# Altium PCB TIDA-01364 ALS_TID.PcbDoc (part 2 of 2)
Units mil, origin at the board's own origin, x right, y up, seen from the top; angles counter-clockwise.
Board outline 5000 x 4000 mil, 4 copper layers (Layer 1 - Top Layer, Layer 2 - GND, Layer 3 - PWR, Layer 4 - Bottom Layer), stack 61.434 mil thick; 133 components, 87 nets, 390 pads, 185 vias.
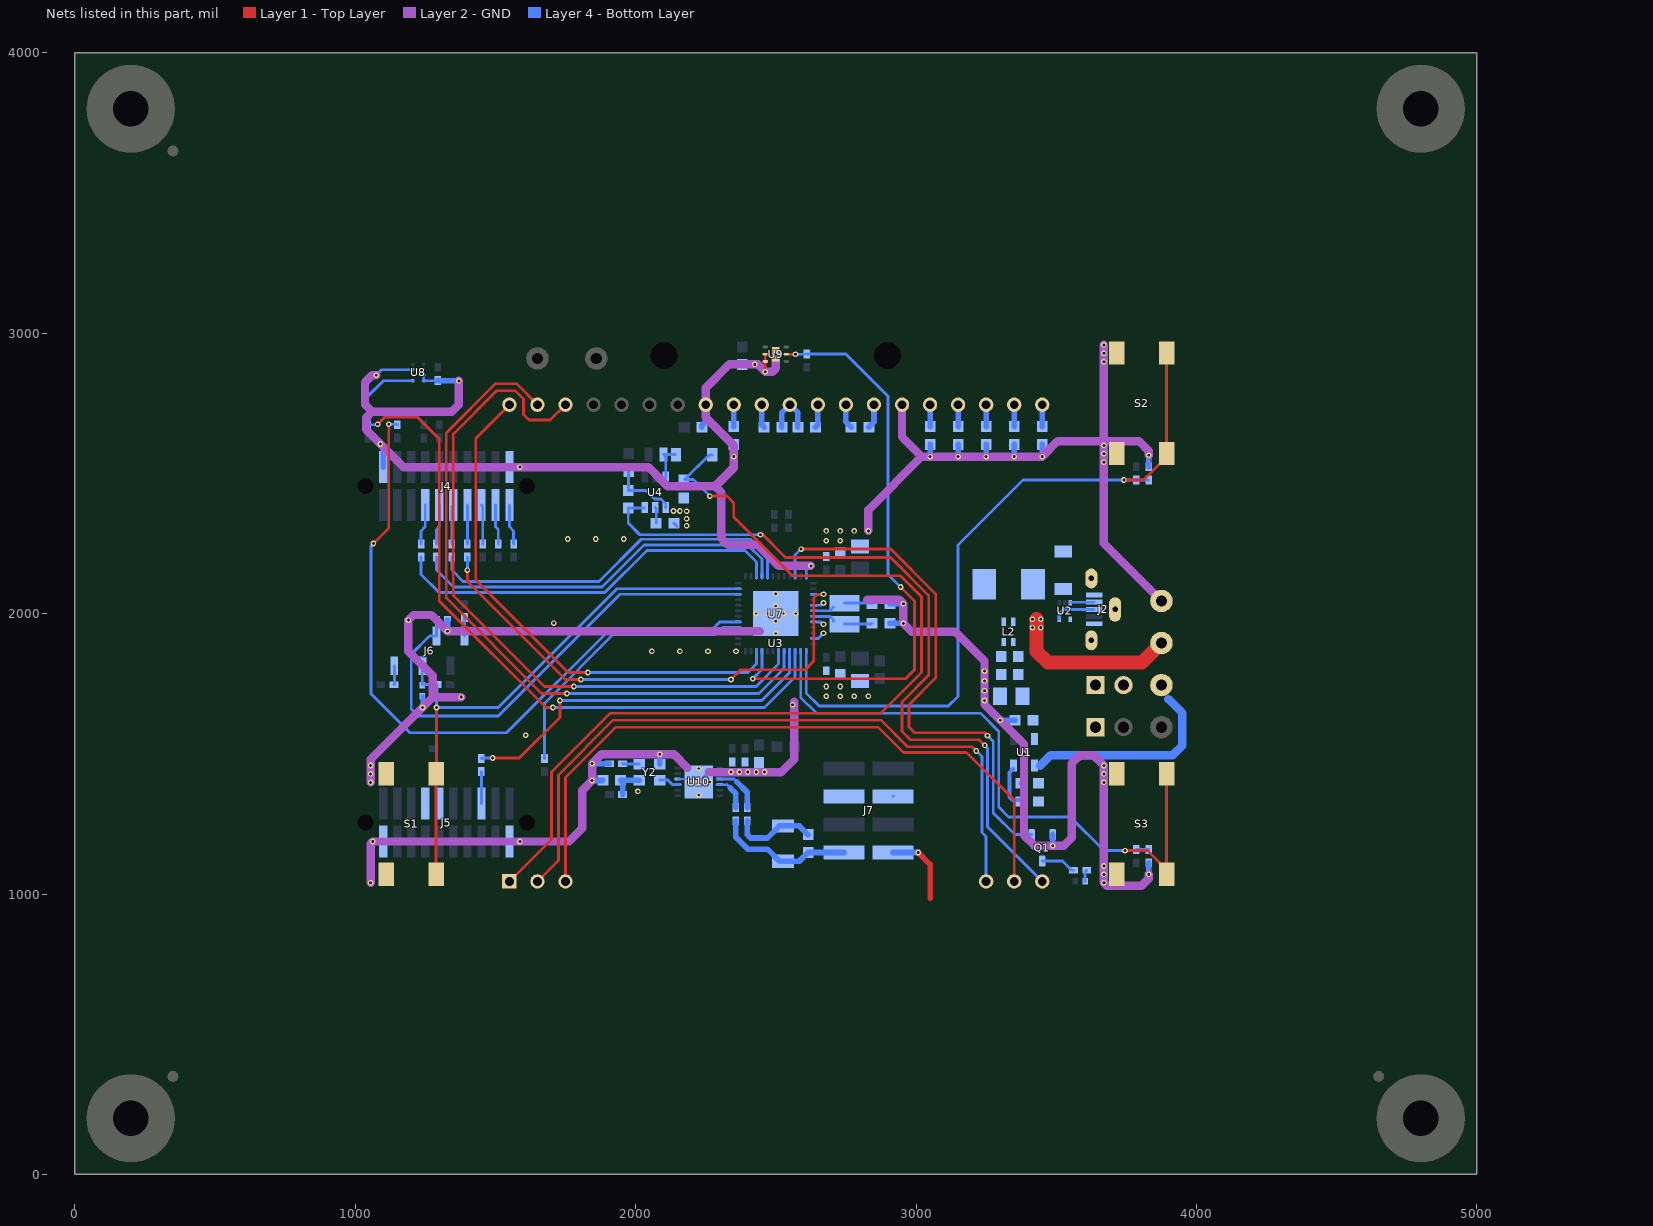
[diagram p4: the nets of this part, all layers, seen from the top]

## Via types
v1: diameter 20, hole 10, Layer 1 - Top Layer to Layer 4 - Bottom Layer, tented both sides, 171 vias
v2: diameter 19.68, hole 7.87, Layer 1 - Top Layer to Layer 4 - Bottom Layer, tented both sides, 14 vias

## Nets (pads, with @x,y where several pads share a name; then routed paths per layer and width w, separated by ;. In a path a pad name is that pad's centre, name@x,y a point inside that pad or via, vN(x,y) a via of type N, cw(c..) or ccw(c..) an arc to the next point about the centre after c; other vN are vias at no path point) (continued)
GND: C2.2 C3.2 C4.2 C6.2 C7.2 C9.2 C10.2 C12.2 C13.2 C14.2 C15.2 C16.2 C17.1 C18.1 C19.2 C20.1 C21.1 C22.2 C23.1 C24.1 C25.1 C26.2 C27.2 C28.1 C29.2 C30.2 C31.1 C32.2 C33.2 C35.2 J4.2 J4.20 J5.1 J5.19 J6.5 L3.2 Q1.2 R27.2 R28.1 S1.3 S1.4 S2.3 S2.4 S3.3 S3.4 TP4.1 U1.2 U3.26 U3.33 U4.4 U5.2 U6.2 U7.36 U7.41 U7.44 U7.47 U7.49 U8.B2 U8.C1 U8.D1 U9.2 U9.3 U9.7 U10.4 U10.8 U10.13 Y2.2 | length 14551.3
  Layer 1 - Top Layer w10: v1(2462.6,2862.4) U9.3@2462.6,2899.21 U9.2@2462.6,2925
  Layer 2 - GND w30: v1(1055,1040) 1055,1180 v1(1062.48,1187.48) v1(1587.52,1187.48) 1762.48,1187.48 1810,1235 1810,1370 v1(1845,1405) v1(1845,1465) 1878.58,1498.58 v1(2086.42,1498.58) 2136.42,1498.58 2185,1450 ; v1(1055,1398.27) v1(1055,1428.27) v1(1055,1458.27) 1055,1480 v1(1240,1665) 1277.3,1702.3 ; v1(1075,2850) 1060,2850 1035,2825 1035,2745 1060,2720 ; v1(1370,2830) 1370,2745 1345,2720 1060,2720 ; v1(1378.38,1702.3) 1277.3,1702.3 ; 2260,1435 v1(2340,1435) v1(2370,1435) v1(2400,1435) v1(2430,1435) v1(2460,1435) 2520,1435 2565,1480 2565,1685 ; 2442.13,1937.13 v1(1329.37,1937.13) 1271.5,1995 1207.87,1995 v1(1189.69,1976.81) 1189.69,1865.31 1277.3,1777.7 1277.3,1702.3 ; v2(2500,2925) 2500,2875 2487.4,2862.4 v1(2462.6,2862.4) 2436.5,2888.5 v1(2425,2888.5) 2333.5,2888.5 2250,2805 U3.33@2250,2745 2250,2700 2350,2600 v1(2350,2560) 2350,2520 2284,2454 ; v1(2625,2170) 2510,2170 2435,2245 2330,2245 2305,2270 2305,2433 2284,2454 ; 2825,2050 2940,2050 v1(2955,2035) v1(2955,1965) 2985,1935 3140,1935 3244,1831 v1(3244,1795) v1(3244,1760) v1(3244,1725) v1(3244,1690) 3244,1676.01 v1(3300,1620) 3385,1535.01 v1(3385,1500) 3385,1209.32 3421.91,1172.4 v1(3487.4,1172.4) 3527.4,1172.4 3555,1200 3555,1465 3585,1495 3633.27,1495 v1(3670,1458.27) v1(3670,1428.27) v1(3670,1398.27) v1(3670,1100) v1(3670,1070) v1(3670,1040) 3680.01,1030 3805,1030 3830,1055 v1(3830,1070) ; v1(2830,2295) 2830,2370 3020,2560 ; U3.26@2950,2745 2950,2630 3020,2560 ; v1(3670,2958.27) v1(3670,2928.27) v1(3670,2898.27) 3670,2615 ; v1(3830,2565) 3830,2580 3795,2615 3670,2615 ; TP4.1@3875,2045 3670,2250 v1(3670,2540) v1(3670,2570) v1(3670,2600) 3670,2615 ; 1060,2720 1040,2700 1040,2655 v1(1090,2605) 1172.48,2522.52 v1(1587.52,2522.52) 2045.48,2522.52 2114,2454 2284,2454 ; 3020,2560 v1(3050,2560) v1(3150,2560) v1(3250,2560) v1(3350,2560) v1(3450,2560) 3505,2615 3670,2615
  Layer 4 - Bottom Layer w8: U10.4@2150.2,1409.84 2215.16,1409.84 v2(2225,1400) 2254.53,1429.53 U10.8@2299.8,1429.53
  Layer 4 - Bottom Layer w10: v1(1075,2850) 1094.85,2869.85 U8.B2@1205.31,2869.85 ; U8.C1@1244.68,2850.16 U8.D1@1244.68,2830.48 C28.1@1289.09,2830.48 ; C28.1@1289.09,2825.48 C28.1@1295,2831.38 ; R28.1@1974,2439.5 R28.1@1974.99,2439.5 ; C7.2@1975,2507.5 R28.1@1975,2439.5 ; U4.4@2107,2379.33 U4.4@2107.46,2378.87 U4.4@2107.46,2385.36 ; U4.4@2107,2392.3 2090.3,2409 2067,2409 2036.5,2439.5 R28.1@1974.99,2439.5 ; C35.2@2136.5,2322 C35.2@2147.5,2311 ; U7.36@2608.27,2127 U7.36@2608.27,2133.86 2608.27,2153.27 v1(2625,2170) ; U7.47@2627,1911.42 U7.47@2633.86,1911.42 2651.42,1911.42 v1(2670,1930) ; U7.44@2627,1970.47 U7.44@2633.86,1970.47 2661.53,1970.47 v1(2670,1962) ; U7.41@2627,2029.53 U7.41@2633.86,2029.53 2661.53,2029.53 v1(2670,2038)
  Layer 4 - Bottom Layer w15: v1(1240,1665) U6.2@1240,1705.32 ; C3.2@3373.5,1395 3385,1406.5 U1.2@3385,1457.76 v1(3385,1500)
  Layer 4 - Bottom Layer w20: v1(1062.48,1187.48) J5.19@1100,1187.48 ; v1(1090,2605) 1100,2595 J4.20@1100,2522.52 ; J6.5@1189.69,1919.96 v1(1189.69,1976.81) ; C28.1@1295,2831.38 1296.38,2830 v1(1370,2830) ; v1(1329.37,1937.13) U5.2@1329.37,1976.81 ; C23.1@1338.62,1702.3 v1(1378.38,1702.3) ; J5.1@1550,1187.48 v1(1587.52,1187.48) ; J4.2@1550,2522.52 v1(1587.52,2522.52) ; v1(1845,1405) C32.2@1883.5,1405 ; v1(1845,1465) R27.2@1906.38,1465 ; Y2.2@2086.42,1463.54 v1(2086.42,1498.58) ; C6.2@2236.5,2665 2236.5,2671.5 2250,2685 U3.33@2250,2745 ; v1(2350,2560) C9.2@2350,2603.5 ; C27.2@2906.5,1965 v1(2955,1965) ; C26.2@2906.5,2035 v1(2955,2035) ; v1(3050,2560) C10.2@3050,2603.5 ; v1(3150,2560) C12.2@3150,2603.5 ; v1(3250,2560) C13.2@3250,2603.5 ; v1(3300,1620) C4.2@3353.5,1620 ; v1(3350,2560) C14.2@3350,2603.5 ; v1(3450,2560) C15.2@3450,2603.5 ; v1(3487.4,1172.4) Q1.2@3487.4,1212.24 ; v1(3830,1070) C25.1@3830,1111.38 ; C24.1@3830,2523.62 v1(3830,2565)
  Layer 4 - Bottom Layer w25: C29.2@2380,2888.5 v1(2425,2888.5)
  other v1: 2008,1366 1608,1566 2560,1675 2680,1705 2730,1705 2780,1705 2830,1705 2680,1740 2730,1740 2058,1866 2158,1866 2258,1866 2358,1866 1708,1966 2680,2260 2730,2260 1758,2266 1858,2266 1958,2266 2680,2295 2730,2295 2780,2295 2182,2313 2182,2338 2182,2365 2135,2366 2158,2366
  other v2: 2225,1352.76 2185.63,1400 2264.37,1400 2225,1447.24 2500,1929.13 2500,1972.44 2429.13,2000 2472.44,2000 2527.56,2000 2570.87,2000 2500,2027.56 2500,2070.87
HDC_DRDY: R23.1 U7.3 U8.D2 | length 2730.7
  Layer 1 - Top Layer w10: v1(1080,2675) 1105,2700 1222.5,2700 1300,2622.5 1300,2045 1680,1665 v1(1705,1665)
  Layer 4 - Bottom Layer w10: v1(1080,2675) 1078.62,2673.62 R23.1@1045,2673.62 1045,2775 1100.48,2830.48 U8.D2@1205.31,2830.48 ; v1(1705,1665) 2460,1665 2568.9,1773.9 U7.3@2568.9,1866.14 U7.3@2568.9,1873
HFXIN: C26.1 U7.42 Y1.1 | length 183.9
  Layer 4 - Bottom Layer w10: U7.42@2627,2009.84 2692.84,2009.84 Y1.1@2706,2023 ; Y1.1@2745,2037.4 2841.1,2037.4 C26.1@2843.5,2035
HFXOUT: C27.1 U7.43 Y1.2 | length 187.9
  Layer 4 - Bottom Layer w10: U7.43@2627,1990.16 2692.84,1990.16 2706,1977 Y1.2@2706,1973 ; Y1.2@2745,1962.6 2841.1,1962.6 C27.1@2843.5,1965
IN0A: R24.2 U10.9 | length 181.8
  Layer 4 - Bottom Layer w10: U10.9@2290,1409.84 U10.9@2299.8,1409.84 2351.16,1409.84 2361,1400
  Layer 4 - Bottom Layer w20: 2361,1400 2398,1363 R24.2@2398,1308.62
IN0A_1: C34.1 L7.2 R24.1 | length 302.2
  Layer 4 - Bottom Layer w20: R24.1@2398,1261.38 2398,1212 2410,1200 2470,1200 2512.99,1242.99 L7.2@2525,1242.99 2583.5,1242.99 C34.1@2615,1211.5
IN0B: R26.2 U10.10 | length 130.3
  Layer 4 - Bottom Layer w10: U10.10@2290,1390 2325.84,1390.16 2337,1379
  Layer 4 - Bottom Layer w20: 2337,1379 2357,1359 R26.2@2357,1308.62
IN0B_1: C34.2 J7.8 L7.1 R26.1 | length 481.3
  Layer 4 - Bottom Layer w20: R26.1@2357,1261.38 2357,1203 2400,1160 2470,1160 L7.1@2512.99,1117.01 ; L7.1@2525,1117.01 2583.5,1117.01 C34.2@2615,1148.5 2615.5,1148 J7.8@2743.1,1148
IN1B_1: J7.4
LCD_A0: U3.38 U7.6 | length 2518.4
  Layer 1 - Top Layer w10: U3.38@1750,2745 1695,2690 1620,2690 1600,2710 1600,2765 1570,2795 1505,2795 1350,2640 1350,2065 1675,1740 v1(1780,1740)
  Layer 4 - Bottom Layer w10: v1(1780,1740) 2430,1740 2509.84,1819.84 U7.6@2509.84,1866.14 U7.6@2509.84,1873
LED_1: Q1.1 U7.34 | length 1917.9
  Layer 1 - Top Layer w10: v1(2590,2230) 2910,2230 3070,2070 3070,1770 2975,1675 2975,1595 2995,1575 3245,1575 v1(3255,1565)
  Layer 4 - Bottom Layer w10: U7.34@2568.9,2127 U7.34@2568.9,2133.86 2568.9,2208.9 v1(2590,2230) ; v1(3255,1565) 3275,1545 3275,1290 3352.76,1212.24 Q1.1@3412.6,1212.24
LED_CA1: U3.2 U3.18 | length 2506.9
  Layer 1 - Top Layer w10: U3.2@1650,1045 1725,1120 1725,1425 1920,1620 2875,1620 2970,1525 3200,1525 v1(3215,1510)
  Layer 4 - Bottom Layer w10: v1(3215,1510) 3235,1490 3235,1220 3250,1205 U3.18@3250,1045
LED_CA2: U3.3 U3.19 | length 2442.3
  Layer 1 - Top Layer w10: U3.3@1750,1045 1750,1415 1930,1595 2865,1595 2955,1505 3180,1505 3350,1335 U3.19@3350,1045
NCSB_LCD: U3.40 U7.10 | length 1877.3
  Layer 1 - Top Layer w10: U3.40@1550,2745 1430,2625 1430,2120 1760,1790 v1(1830,1790)
  Layer 4 - Bottom Layer w10: v1(1830,1790) 2400,1790 2431.1,1821.1 U7.10@2431.1,1866.14 U7.10@2431.1,1873
NCSB_RF: R12.2 U7.39 | length 1802
  Layer 1 - Top Layer w10: v1(1400,2155) 1400,2115 1750,1765 v1(1805,1765) ; v1(2340,1765) 2375,1800 2605,1800 2635,1830 2635,2055 2648.9,2068.9 v1(2670,2068.9)
  Layer 4 - Bottom Layer w10: v1(1400,2155) R12.2@1400,2201.38 ; v1(1805,1765) v1(2340,1765) ; U7.39@2627,2068.9 U7.39@2633.86,2068.9 v1(2670,2068.9)
NetC2_1: C2.1 J1.1 L1.2
NetC4_1: C4.1 J3.1 U1.5
NetC5_1: C5.1 U3.31 | length 83.5
  Layer 4 - Bottom Layer w20: U3.31@2450,2745 2450,2673.5 C5.1@2458.5,2665
NetC5_2: C5.2 C8.1 U3.30 | length 183.6
  Layer 4 - Bottom Layer w20: C5.2@2521.5,2665 2521.5,2716.5 U3.30@2550,2745 2578.5,2716.5 C8.1@2578.5,2665
NetC8_2: C8.2 U3.29 | length 83.5
  Layer 4 - Bottom Layer w20: C8.2@2641.5,2665 2650,2673.5 U3.29@2650,2745
NetC9_1: C9.1 U3.32 | length 78.5
  Layer 4 - Bottom Layer w20: C9.1@2350,2666.5 U3.32@2350,2745
NetC10_1: C10.1 U3.25 | length 78.5
  Layer 4 - Bottom Layer w20: C10.1@3050,2666.5 U3.25@3050,2745
NetC11_1: C11.1 U3.28 | length 87.7
  Layer 4 - Bottom Layer w20: U3.28@2750,2745 2750,2683.5 C11.1@2768.5,2665
NetC11_2: C11.2 U3.27 | length 87.7
  Layer 4 - Bottom Layer w20: C11.2@2831.5,2665 2850,2683.5 U3.27@2850,2745
NetC12_1: C12.1 U3.24 | length 78.5
  Layer 4 - Bottom Layer w20: C12.1@3150,2666.5 U3.24@3150,2745
NetC13_1: C13.1 U3.23 | length 78.5
  Layer 4 - Bottom Layer w20: C13.1@3250,2666.5 U3.23@3250,2745
NetC14_1: C14.1 U3.22 | length 78.5
  Layer 4 - Bottom Layer w20: C14.1@3350,2666.5 U3.22@3350,2745
NetC15_1: C15.1 U3.21 | length 78.5
  Layer 4 - Bottom Layer w20: C15.1@3450,2666.5 U3.21@3450,2745
NetC16_1: C16.1 D2.1 U3.1 | length 3372.3
  Layer 1 - Top Layer w10: U3.1@1550,1045 1700,1195 1700,1435 1910,1645 2875,1645 3020,1790 3020,2060 2945,2135 2560,2135 2350,2345 2350,2394.7 2325.7,2419 v1(2265,2419)
  Layer 4 - Bottom Layer w10: v1(2265,2419) 2206,2478 2174.5,2478 2262.5,2566 D2.1@2273.47,2566
NetC32_1: C32.1 R25.1 Y2.4 | length 120.6
  Layer 4 - Bottom Layer w10: C32.1@1946.5,1405 C32.1@1947.95,1406.46
  Layer 4 - Bottom Layer w20: C32.1@1946.5,1405 1953.62,1397.87 R25.1@1953.62,1355 ; C32.1@1947.95,1406.46 Y2.4@2013.58,1406.46
NetC35_1: C35.1 U4.5 | length 58.3
  Layer 4 - Bottom Layer w10: U4.5@2070.06,2378.87 2073.5,2375.42 C35.1@2073.5,2322
NetD2_2: D2.2 L4.2 U4.3 | length 125.3
  Layer 4 - Bottom Layer w10: U4.3@2107.46,2487.13 2107.46,2559.24 L4.2@2099.45,2567.25 D2.2@2141.28,2567.25
NetD3_1: D3.1 J5.12 J5.14
NetD4_1: D4.1 R21.2 | length 42.4
  Layer 4 - Bottom Layer w10: D4.1@3602.72,1045 3602.72,1079.09 R21.2@3608.62,1085
NetJ4_1: J4.1 R15.2 | length 145.1
  Layer 4 - Bottom Layer w10: J4.1@1550,2387.48 1550,2310 1565,2295 R15.2@1565,2248.62
NetJ4_3: J4.3 R14.1 | length 143
  Layer 4 - Bottom Layer w10: J4.3@1500,2387.48 1500,2310 1510,2300 R14.1@1510,2248.62
NetJ4_5: J4.5 R13.1 | length 140.9
  Layer 4 - Bottom Layer w10: J4.5@1450,2387.48 1455,2382.48 R13.1@1455,2248.62
NetJ4_7: J4.7 R12.1 | length 138.9
  Layer 4 - Bottom Layer w10: R12.1@1400,2248.62 J4.7@1400,2387.48
NetJ4_9: J4.9 R8.2 | length 140.9
  Layer 4 - Bottom Layer w10: R8.2@1345,2248.62 1345,2382.48 J4.9@1350,2387.48
NetJ4_11: J4.11 R7.2 | length 143
  Layer 4 - Bottom Layer w10: R7.2@1290,2248.62 1290,2300 1300,2310 J4.11@1300,2387.48
NetJ4_13: J4.13 R5.1 | length 145.1
  Layer 4 - Bottom Layer w10: R5.1@1235,2248.62 1235,2295 1250,2310 J4.13@1250,2387.48
NetJ5_6: J5.6 R11.1 | length 113.9
  Layer 4 - Bottom Layer w10: J5.6@1450,1322.52 R11.1@1450,1436.38
NetJ6_1: J6.1 R3.2 | length 73.2
  Layer 4 - Bottom Layer w10: J6.1@1389.69,1919.96 R3.2@1389.69,1993.19
NetJ6_6: J6.6 R9.2 | length 67.4
  Layer 4 - Bottom Layer w10: R9.2@1138.31,1746.81 1139.69,1748.19 J6.6@1139.69,1813.66
NetL1_1: L1.1 L2.3
NetL2_2: L2.2 L3.1
NetQ1_3: Q1.3 R21.1 | length 124.9
  Layer 4 - Bottom Layer w10: Q1.3@3450,1117.76 3522.24,1117.76 3555,1085 R21.1@3561.38,1085
NetR1_2: R1.2 U1.3 | length 148.4
  Layer 4 - Bottom Layer w15: U1.3@3345,1445 3333,1433 3333,1347 3345,1335 R1.2@3373.5,1335
NetR27_1: R27.1 Y2.1 | length 60.6
  Layer 4 - Bottom Layer w10: R27.1@1953.62,1465 1955.08,1463.54 Y2.1@2013.58,1463.54
NetR28_2: R28.2 U3.20 U4.6 | length 2699.9
  Layer 1 - Top Layer w10: v1(2445.5,2281) 2450,2281 2452,2283 2535,2200 2910,2200 3045,2065 3045,1780 2950,1685 2950,1580 2980,1550 3225,1550 v1(3245,1530)
  Layer 4 - Bottom Layer w10: U4.6@2030.3,2376.5 R28.2@1974,2376.5 1974,2322 2013,2283 2015,2281 v1(2445.5,2281) ; v1(3245,1530) 3255,1520 3255,1240 U3.20@3450,1045
NetU10_3: U10.3 Y2.3 | length 80.3
  Layer 4 - Bottom Layer w10: Y2.3@2086.42,1406.46 2114.54,1406.46 2130.84,1390.16 U10.3@2150.2,1390.16 U10.3@2160,1390.16
NRST_EM: R11.2 U7.4 | length 1344.7
  Layer 1 - Top Layer w10: v1(1490,1485) 1585,1485 1730,1630 v1(1730,1690)
  Layer 4 - Bottom Layer w10: R11.2@1450,1483.62 1451.38,1485 v1(1490,1485) ; v1(1730,1690) 2450,1690 2549.21,1789.21 U7.4@2549.21,1866.14 U7.4@2549.21,1873
NRST_LCD: U3.39 U7.5 | length 2469.5
  Layer 1 - Top Layer w10: U3.39@1650,2745 1575,2820 1500,2820 1325,2645 1325,2055 1665,1715 v1(1755,1715)
  Layer 4 - Bottom Layer w10: v1(1755,1715) 2440,1715 2529.53,1804.53 U7.5@2529.53,1866.14 U7.5@2529.53,1873
OPT_INT: R22.1 U7.9 U9.5 | length 2149.8
  Layer 1 - Top Layer w10: v1(2417.5,1767.5) 2962.5,1767.5 2995,1800 2995,2045 v1(2945,2095) ; U9.5@2537.4,2925 v1(2570,2925)
  Layer 4 - Bottom Layer w10: v1(2417.5,1767.5) 2450.79,1800.79 U7.9@2450.79,1866.14 U7.9@2450.79,1873 ; v1(2570,2925) 2609.39,2925 R22.1@2610,2925.61 2749.39,2925.61 2900,2775 2900,2140 v1(2945,2095)
P3.4: R5.2 U7.27 | length 1420.5
  Layer 4 - Bottom Layer w10: R5.2@1235,2201.38 1235,2140 1300,2075 1890,2075 2040,2225 2390,2225 2431.1,2183.9 U7.27@2431.1,2127
P3.5: R7.1 U7.28 | length 1382.4
  Layer 4 - Bottom Layer w10: R7.1@1290,2201.38 1290,2155 1350,2095 1880,2095 2030,2245 2400,2245 2450.79,2194.21 U7.28@2450.79,2127
P3.6: R8.1 U7.29 | length 1353.1
  Layer 4 - Bottom Layer w10: R8.1@1345,2201.38 1345,2155 1385,2115 1870,2115 2020,2265 2410,2265 2470.47,2204.53 U7.29@2470.47,2127
SBWTCK: J6.3 U5.1 U7.22 | length 1736.7
  Layer 4 - Bottom Layer w10: U5.1@1290,1981.81 1289.69,1981.5 J6.3@1289.69,1919.96 1264.96,1919.96 1200,1855 1200,1660 1225,1635 1510,1635 1943.9,2068.9 U7.22@2373,2068.9
SBWTDIO: C23.2 J6.4 R18.1 S1.1 S1.2 U6.1 U7.23 | length 2055.2
  Layer 1 - Top Layer w10: S1.2@1288.58,1070.87 S1.1@1288.58,1429.13 1290,1430.55 v1(1290,1665)
  Layer 4 - Bottom Layer w10: J6.4@1239.69,1813.66 1239.37,1813.35 1239.37,1746.81 1239.86,1747.3 R18.1@1291.38,1747.3 C23.2@1291.38,1702.3 1290,1700.92 v1(1290,1665) 1510,1665 1933.58,2088.58 U7.23@2366.14,2088.58 U7.23@2373,2088.58
SENSOR1: J7.7 | length 270.5
  Layer 1 - Top Layer w20: v1(3008,1148) 3050,1106.01 3050,985
  Layer 4 - Bottom Layer w20: J7.7@2917.9,1148 v1(3008,1148)
SENSOR2: J7.3 | length 2.8
  Layer 4 - Bottom Layer w10: J7.3@2917.9,1348 J7.3@2919.9,1350
UART_CTS: R2.2 U7.17 | length 2556.5
  Layer 1 - Top Layer w10: v1(1065,2250) 1120,2305 v1(1120,2675)
  Layer 4 - Bottom Layer w10: v1(1065,2250) 1056,2241 1056,1714 1195,1575 1540,1575 1910,1945 2274.53,1945 2300,1970.47 U7.17@2366.14,1970.47 U7.17@2373,1970.47 ; v1(1120,2675) 1148.62,2675 R2.2@1150,2673.62
UART_RTS: R10.1 U7.16 | length 1006.5
  Layer 4 - Bottom Layer w10: R10.1@1675,1483.62 1675,1680 1920,1925 2285,1925 2310.79,1950.79 U7.16@2366.14,1950.79 U7.16@2373,1950.79
USB_D_N: J2.2 U2.3 | length 85.8
  Layer 4 - Bottom Layer w10: U2.3@3549.69,2039.53 3550.75,2040.59 J2.2@3635,2040.59
USB_D_P: J2.3 U2.5 | length 150.6
  Layer 4 - Bottom Layer w10: U2.5@3510.31,1980.47 3510.31,2000.31 3525,2015 J2.3@3635,2015
USB_GND: C1.2 D1.1 J2.5 J2.6 J2.7 J2.8 L2.1 U2.4
USR_BTN_1: C24.2 R19.1 S2.1 S2.2 U7.1 | length 2604.5
  Layer 1 - Top Layer w10: v1(3741.38,2476.38) 3811.38,2476.38 3893.58,2558.58 S2.2@3893.58,2570.86 S2.1@3893.58,2929.13
  Layer 4 - Bottom Layer w10: U7.1@2608.27,1873 U7.1@2608.27,1866.14 2608.27,1716.73 2655,1670 3115,1670 3150,1705 3150,2245 3381.38,2476.38 v1(3741.38,2476.38) R19.1@3785,2476.38 C24.2@3830,2476.38
USR_BTN_2: C25.2 R20.1 S3.1 S3.2 U7.2 | length 2334.3
  Layer 1 - Top Layer w10: v1(3745,1155) 3825,1155 S3.2@3893.58,1086.42 ; S3.2@3893.58,1070.87 S3.2@3893.58,1086.42 ; S3.1@3893.58,1429.13 S3.2@3893.58,1086.42
  Layer 4 - Bottom Layer w10: U7.2@2588.58,1873 U7.2@2588.58,1866.14 2588.58,1701.42 2645,1645 3230,1645 3295,1580 3295,1310 3330,1275 3550,1275 3670,1155 v1(3745,1155) 3781.38,1155 R20.1@3785,1158.62 C25.2@3830,1158.62
V_INPUT: C3.1 J1.2 R1.1 TP2.1 U1.1 | length 723.3
  Layer 4 - Bottom Layer w30: 3442.49,1457.49 3480,1495 3915,1495 3950,1530 3950,1645 3900,1695
VBUS: C1.1 D1.2 J2.1 L2.4 TP1.1 | length 605.6
  Layer 1 - Top Layer w50: 3430,1980 3430,1865 3470,1825 3805,1825 TP1.1@3875,1895
  other v1: 3415,1950 3445,1950 3415,1980 3445,1980
pads on no net: FID1.1 FID2.1 FID3.1 FID4.1 FID5.1 FID6.1 H1.1 H2.1 H3.1 H4.1 H5.0 H6.0 H7.0 H8.0 J2.4 J4.4 J4.6 J4.8 J4.10 J4.15 J4.16 J4.17 J4.19 J4.MH1 J4.MH2 J5.2 J5.4 J5.5 J5.7 J5.8 J5.9 J5.10 J5.11 J5.13 J5.15 J5.16 J5.17 J5.18 J5.20 J5.MH1 J5.MH2 J7.1 J7.2 J7.5 J7.6 SH-J1.0 SH-J2.0 SH-J3.0 SH-J4.0 U1.4 U2.1 U2.2 U7.7 U7.8 U7.12 U7.13 U7.14 U7.15 U7.30 U7.33 U7.35 U7.38 U7.40 U7.45 U7.46 U8.C2 U10.11 U10.12

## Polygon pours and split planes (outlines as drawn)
GND on Layer 4 - Bottom Layer "GND_L04_P012" (solid, remove dead copper, pour order 12): 2188.73,2294.73 2104,2294.73 2104,2348 2098,2354 2092,2360 2092,2403 2137.73,2403 2144.73,2410 2168.73,2434 2194,2434 2194,2382.98 2193.02,2382 2193.02,2299.02
NetC4_1 on Layer 4 - Bottom Layer "Layer 1 - CIN1 - Top Layer-No Net" (solid, remove dead copper, pour order 10): 3655,1645 3390,1645 3390,1545 3410,1525 3655,1525 3675,1545 3675,1625
GND on Layer 2 - GND "GND_L02_P014" (solid, remove dead copper, pour order 14): 2193,2331 2193,2398 2120.1,2398 2107.46,2385.36 2108,2384.82 2108,2331 2168,2331
GND on Layer 2 - GND "Layer 2 - GND- GND" (solid, remove dead copper, pour order 8): 2275,1340 1610,1340 1550,1400 1550,2105 1780,2335 2375,2335 2410,2300 2580,2130 2580,1665 2580,1475 2525,1420 2275,1420
GND on Layer 2 - GND "Layer 2 - SHLD1 - GND-GND" (solid, remove dead copper, pour order 9): 3005,1655 2375,1655 2375,2310 3005,2310
GND on Layer 3 - PWR "Layer 2 - GND- GND" (solid, remove dead copper, pour order 7): 2275,1340 1610,1340 1550,1400 1550,2105 1780,2335 2375,2335 2410,2300 2580,2130 2580,1665 2580,1475 2525,1420 2275,1420
GND on Layer 1 - Top Layer "Layer 2 - GND- GND" (solid, remove dead copper, pour order 6): 2275,1340 1610,1340 1550,1400 1550,2105 1780,2335 2375,2335 2410,2300 2580,2130 2580,1665 2580,1475 2525,1420 2275,1420

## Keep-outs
Keep-Out Layer:
  text ".Layer_Name" at 577,-858.49 h60

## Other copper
Layer 1 - Top Layer:
  region net SENSOR1: 400,0 400,400 1000,400 1000,1000 4000,1000 4000,3000 1000,3000 1000,400 0,400 0,3600 400,3600 400,4000 4600,4000 4600,3600 5000,3600 5000,400 4600,400 4600,0
  region net GND: 3745,2525 3655,2525 3655,2615 3745,2615
  region net GND: 3745,2883.27 3655,2883.27 3655,2973.27 3745,2973.27
  region net GND: 3745,1025 3655,1025 3655,1115 3745,1115
  region net GND: 1140,1383.27 1040,1383.27 1040,1473.27 1140,1473.27
  region net GND: 1140,1025 1040,1025 1040,1115 1140,1115
  region net GND: 3745,1383.27 3655,1383.27 3655,1473.27 3745,1473.27
  text ".Layer_Name" at 577,-858.49 h60
Layer 2 - GND:
  region net GND: 2175,1340 2275,1340 2275,1460 2175,1460
Layer 3 - PWR:
  region net 3P3V: 3700,1545 3700,1625 3720,1645 3900,1645 3920,1625 3920,1545 3900,1525 3720,1525
Layer 4 - Bottom Layer:
  region net USB_GND: 3535,1990 3571,1990 3593,1968 3678,1968 3685,1975 3685,2075 3675,2085 3615,2085 3600,2100 3600,2155 3570,2185 3355,2185 3322,2152 3322,1947 3310,1935 3212,1935 3200,1947 3200,2225 3280,2305 3660,2305 3755,2210 3755,1890 3725,1860 3550,1860 3535,1875
  region net NetL1_1: 3338,1825 3385,1825 3385,1895 3360,1920 3338,1920
  region net NetL2_2: 3325,1825 3285,1825 3285,1895 3310,1920 3325,1920
  region net GND: 3324,1805 3324,1675 3229,1675 3229,1805
  region net NetD3_1: 1235,1265 1315,1265 1315,1425 1290,1450 1260,1450 1235,1425
  region net AVCC: 2622,1897 2622,1868 2665,1825 2750,1825 2775,1800 2890,1800 2890,1910 2673,1910 2660,1897
  region net GND: 2665,1815 2740,1815 2770,1785 2840,1785 2840,1690 2675,1690 2665,1700
  region net 3P3V: 2622,2103 2622,2132 2665,2175 2750,2175 2775,2200 2840,2200 2840,2090 2673,2090 2660,2103
  region net GND: 2665,2185 2740,2185 2770,2215 2840,2215 2840,2310 2675,2310 2665,2300
  region net 3P3V: 3700,1545 3700,1625 3720,1645 3900,1645 3920,1625 3920,1545 3900,1525 3720,1525
  region net 3P3V: 2195,2645 2195,2750 2170,2775 2025,2775 2005,2755 2005,2665 2025,2645
  region net 3P3V: 1954.5,2626 2009.5,2626 2009.5,2550 1954.5,2550
  region net 3P3V: 1260,1500 1270,1490 1340,1490 1340,1555 1270,1555 1260,1545
  region net NetC2_1: 3345,1805 3345,1680 3360,1665 3655,1665 3675,1685 3675,1785 3655,1805
  region net VBUS: 3338,1947 3350,1935 3458,1935 3470,1947 3470,2047 3489,2066 3560,2066 3565.5,2060.5 3569,2057 3665,2057 3665,2075 3604,2075 3582,2097 3582,2140 3562,2160 3352,2160 3338,2146
  region net V_INPUT: 3700,1685 3700,1785 3720,1805 3900,1805 3925,1780 3925,1680 3910,1665 3720,1665
  region net V_INPUT: 3409,1316 3420,1305 3460,1305 3470,1315 3470,1464 3449,1485 3409,1485
  region net GND: 2275,1424 2464,1424 2470,1430 2470,1490 2420,1490 2335,1490 2325,1480 2325,1445 2315,1435 2275,1435
  region net AVCC_FLT: 2310,1444 2314,1448 2314,1484 2330,1500 2530,1500 2530,1570 2525,1575 2315,1575 2288,1548 2288,1444
  region net 3P3V: 2545,1500 2560,1485 2630,1485 2630,1555 2610,1575 2550,1575 2545,1570
  text ".Layer_Name" at 577,-858.49 h60

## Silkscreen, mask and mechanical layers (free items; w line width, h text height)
Top Overlay:
  text "USR_BTN" at 3650,3065 h75
  text "1" at 3790,2990 h75
  text "RESET" at 1095,965 h75
  text "USR_BTN" at 3650,965 h75
  text "2" at 3790,890 h75
  text "TIDA-01364" at 2225,225 h100
  text ".Layer_Name" at 577,-858.49 h60
Bottom Overlay:
  text "B0_SDA" at 1730,3005 h50
  text "B0_SCL" at 1935,3005 h50
  text "GND" at 4130,1990 h75
  text "VBUS" at 4170,1840 h75
  text "1" at 1424,1766 h40
  text "V_INPUT" at 4270,1690 h75
  text "3v3" at 4100,1540 h75
  text "CIN1" at 3240,1330 h75
  text "CIN2" at 3240,1130 h75
  text "2016" at 1950,175 h100
  text "©" at 2050,175 h105
  text "Rev. E1" at 2575,175 h100
  text ".Layer_Name" at 577,-858.49 h60
Top Paste:
  text ".Layer_Name" at 577,-858.49 h60
Bottom Paste:
  text ".Layer_Name" at 577,-858.49 h60
Top Solder:
  text ".Layer_Name" at 577,-858.49 h60
  text ".Layer_Name" at 577,-858.49 h60
Bottom Solder:
  text ".Layer_Name" at 577,-858.49 h60
Drill Guide:
  text ".Layer_Name" at 577,-858.49 h60
M1 Board Outline:
  lines w10: -5,0 ccw(c0,0) 0,-5 ; -5,0 ccw(c0,0) 0,-5 ; -5,0 ccw(c0,0) 0,-5 ; -5,0 ccw(c0,0) 0,-5 ; -5,0 ccw(c0,0) 0,-5 ; -5,0 ccw(c0,0) 0,-5 ; -5,0 ccw(c0,0) 0,-5 ; -5,0 ccw(c0,0) 0,-5 ; -5,4000 cw(c0,4000) 0,4005 ; -5,4000 cw(c0,4000) 0,4005 ; -5,4000 cw(c0,4000) 0,4005 ; -5,4000 cw(c0,4000) 0,4005 ; -5,4000 cw(c0,4000) 0,4005 ; -5,4000 cw(c0,4000) 0,4005 ; -5,4000 cw(c0,4000) 0,4005 ; -5,4000 cw(c0,4000) 0,4005 ; 5000,-5 ccw(c5000,0) 5005,0 ; 5000,-5 ccw(c5000,0) 5005,0 ; 5000,-5 ccw(c5000,0) 5005,0 ; 5000,-5 ccw(c5000,0) 5005,0 ; 5000,-5 ccw(c5000,0) 5005,0 ; 5000,-5 ccw(c5000,0) 5005,0 ; 5000,-5 ccw(c5000,0) 5005,0 ; 5000,-5 ccw(c5000,0) 5005,0 ; 5000,4005 cw(c5000,4000) 5005,4000 ; 5000,4005 cw(c5000,4000) 5005,4000 ; 5000,4005 cw(c5000,4000) 5005,4000 ; 5000,4005 cw(c5000,4000) 5005,4000 ; 5000,4005 cw(c5000,4000) 5005,4000 ; 5000,4005 cw(c5000,4000) 5005,4000 ; 5000,4005 cw(c5000,4000) 5005,4000 ; 5000,4005 cw(c5000,4000) 5005,4000 ; 1135,2760 1135,2790 1315,2790 1315,2760 1135,2760 ; 1135,2945 1315,2945 1315,2975 1135,2975 1135,2945
  lines w20: -10,0 ccw(c0,0) 0,-10 ; -10,0 ccw(c0,0) 0,-10 ; -10,0 -10,4000 ; -10,4000 cw(c0,4000) 0,4010 ; -10,4000 cw(c0,4000) 0,4010 ; 0,-10 5000,-10 ; 0,4010 5000,4010 ; 5000,-10 ccw(c5000,0) 5010,0 ; 5000,-10 ccw(c5000,0) 5010,0 ; 5000,4010 cw(c5000,4000) 5010,4000 ; 5000,4010 cw(c5000,4000) 5010,4000 ; 5010,0 5010,4000 ; 0,0 0,4000 5000,4000 5000,0 0,0
  text ".Layer_Name" at 577,-858.49 h60
M2 Board Dimensions:
  rectangle: 0,-275 125,-150
  rectangle: 125,-400 500,-275
  lines w7: 0,-275 1000,-275 ; 125,-400 125,-150 ; 250,-400 250,-150 ; 500,-400 500,-150 ; 750,-400 750,-150 ; 0,-400 1000,-400 1000,-150 0,-150 0,-400
  text ".Layer_Name" at 577,-858.49 h60
M3 3D STEP Top:
  text ".Layer_Name" at 577,-858.49 h60
M4 3D STEP Bottom:
  text ".Layer_Name" at 577,-858.49 h60
M5 Assembly Top:
  lines w10: -292,-930.17 6308,-930.17 ; -292,-726.83 6310,-726.83 ; -292,-523.5 -292,-1133.5 3713,-1133.5 6310,-1133.5 6310,-523.5 -291.5,-523.5 -291.5,-1133.5 1284,-1133.5 ; 2173,-1133.5 2173,-523.5 ; 3440,-726.83 3440,-523.5 ; 4280,-726.83 4280,-523.5 ; 4902,-1140 4902,-937.17
  text "COMPONENTS MARKED 'DNP' SHOULD NOT BE POPULATED." at 1153.5,-318.5 h60
  text "ASSEMBLY VARIANT:" at 1153,-434 h60
  text ".VariantName" at 2189,-434 h60
  text "PCB VIEWED FROM TOP SIDE" at -228.5,-655.67 h60
  text "BOARD #:" at 2248,-655.67 h60
  text ".PRJ_Number" at 2793.5,-655.67 h60
  text "REV:" at 3638,-655.67 h60
  text ".PCB_Rev" at 3929.5,-655.67 h60
  text "SVN REV:" at 4476,-655.67 h60
  text ".VersionControl_RevNumber" at 4982,-655.67 h60
  text "PLOT NAME =" at -228.5,-1064.34 h60
  text ".plot_File_Name" at 577,-1064.34 h60
  text "GENERATED    :" at 2250,-1064.34 h60
  text ".Print_Date" at 3119.5,-1064.34 h60
  text ".Print_Time" at 3848.5,-1064.34 h60
  text "TEXAS INSTRUMENTS" at 5113,-1064.34 h60
M6 Assembly Bottom:
  lines w10: -292.5,-727.33 6309.5,-727.33 ; -290.5,-930.67 6309.5,-930.67 ; 1115.5,-1140.5 1115.5,-937.67 ; 1737.5,-727.33 1737.5,-524 ; 2577.5,-727.33 2577.5,-524 ; 3844.5,-1134 3844.5,-524 ; 4733.5,-1134 6309,-1134 6309,-524 -292.5,-524 -292.5,-1134 2304.5,-1134 6309.5,-1134 6309.5,-524
  text "COMPONENTS MARKED 'DNP' SHOULD NOT BE POPULATED." at 6102,-318 h60
  text ".VariantName" at 5058,-434 h60
  text "ASSEMBLY VARIANT:" at 6097,-434 h60
  text ".VersionControl_RevNumber" at 1035.5,-656.17 h60
  text "SVN REV:" at 1541.5,-656.17 h60
  text ".PCB_Rev" at 2088,-656.17 h60
  text "REV:" at 2379.5,-656.17 h60
  text ".PRJ_Number" at 3224,-656.17 h60
  text "BOARD #:" at 3769.5,-656.17 h60
  text "PCB VIEWED FROM BOTTOM SIDE" at 6246,-656.17 h60
  text "TEXAS INSTRUMENTS" at 904.5,-1064.84 h60
  text ".Print_Time" at 2169,-1064.84 h60
  text ".Print_Date" at 2898,-1064.84 h60
  text "GENERATED    :" at 3767.5,-1064.84 h60
  text ".plot_File_Name" at 5440.5,-1064.84 h60
  text "PLOT NAME =" at 6246,-1064.84 h60
M9 Title Sheet:
  drawing of 1178 lines, arcs and shapes, not listed
  text "1" at 739.84,8036.5 h70
  text "2" at 3235.5,8036.5 h70
  text "3" at 5724.84,8036.5 h70
  text "4" at 8231.51,8036.5 h70
  text "5" at 10730.5,8036.5 h70
  text "6" at 13235.5,8036.5 h70
  text "A" at -416.5,6893.5 h70
  text "A" at 14383.5,6893.5 h70
  text "B" at -416.5,4513.5 h70
  text "B" at 14383.5,4513.5 h70
  text "C" at -416.5,2138.5 h70
  text "C" at 14383.5,2138.5 h70
  text "PROJECT TITLE:" at 11343.5,277.5 h45
  text ".PRJ_Title" at 11393.5,144.17 h70
  text "DESIGNED FOR:" at 11343.5,-23.5 h45
  text ".PRJ_Customer" at 11393.5,-163.5 h70
  text "D" at -416.5,-231.5 h70
  text "D" at 14383.5,-231.5 h70
  text "FILE NAME:" at 11343.5,-323.5 h45
  text ".PCB_File_Name_No_Path" at 11393.5,-443.5 h70
  text "Texas Instruments (TI) and/or its licensors do not warrant the accuracy or completeness of this specification" at 6374,-605.34 h45
  text "ENGINEER:" at 11343.5,-613.5 h45
  text "LAYOUT BY:" at 12848.5,-613.5 h45
  text "or any information contained therein. TI and/or its licensors do not warrant that this design will meet" at 6329.01,-718 h45
  text ".PRJ_Engineer" at 11393.5,-768.49 h70
  text ".PCB_Layout" at 12899,-768.49 h70
  text "JMM" at 12850,-800 h100
  text "s  o  l  u  t  i  o  n  s" at 13708,-803 h68
  text "the specifications, will be suitable for your application or fit for any particular purpose, or will operate in" at 6329.01,-830.67 h45
  text ".Layer_Name" at 577,-858.49 h60
  text "ALTIUM DESIGNER VERSION:" at 12848.5,-923.5 h45
  text "an implementation. TI and/or its licensors do not warrant that the design is production worthy. You should" at 6329.01,-943.33 h45
  text "completely validate and test your design implementation to confirm the system functionality for your application." at 6374,-1056 h45
  text ".print_Scale" at 11393.5,-1056.83 h70
  text ".Application_BuildNumber" at 12899,-1056.83 h70
  text "1" at 739.84,-1263.5 h70
  text "2" at 3235.5,-1263.5 h70
  text "3" at 5724.84,-1263.5 h70
  text "4" at 8231.51,-1263.5 h70
  text "5" at 10730.5,-1263.5 h70
  text "6" at 13235.5,-1263.5 h70
M10 Fab Notes:
  drawing of 185 lines, arcs and shapes, not listed
  text "DESIGN INFORMATION" at 12381.02,5910 h60
  text "MIN. TRACK WIDTH:" at 11736.46,5730 h60
  text "8" at 12832.7,5730 h60
  text "MIL" at 12987.46,5730 h60
  text "MIN. CLEARANCE:" at 11736.46,5598 h60
  text "0.2" at 12772.7,5598 h60
  text "mm" at 12987.46,5598 h60
  text "MIN. VIA PAD SIZE:" at 11736.46,5466 h60
  text "24" at 12802.71,5466 h60
  text "MIL" at 12987.46,5466 h60
  text "0.05mm (2MIL)" at 12431.46,5324.29 h60
  text "MINIMUM ANNULAR RING" at 11407.23,5320 h60
  text "EXTERNAL" at 13139.46,5320 h60
  text "PER" at 11607.23,5202 h60
  text "IPC-D-275 CLASS 2 LEVEL C" at 11827.23,5202 h60
  text "MIL, HOLES" at 13315.46,5089.71 h60
  text "+/-" at 12923,5089 h60
  text "+/-" at 13777,5089 h60
  text "REGISTRATION TOLERANCES:" at 11407.23,5084 h60
  text "METAL" at 12607,5084 h60
  text "5" at 13183.2,5084 h60
  text "3" at 14016.2,5084 h60
  text "MIL" at 14132.46,5084 h60
  text "MATERIAL:" at 11332.46,4874.54 h60
  text "FR-4 High Tg" at 12318.9,4734.21 h60
  text "FR-408" at 11753.46,4725.64 h60
  text "X" at 12165.46,4725.64 h60
  text "OTHER" at 13241.46,4725.64 h60
  text "62 MIL (1.6mm) +/-10%" at 12073.56,4562.92 h60
  text "THICKNESS:" at 11407.23,4558.64 h60
  text "X" at 11945.4,4558.64 h60
  text "OTHER" at 13358.46,4558.64 h60
  text "TOLERANCE:" at 11407.23,4400.64 h60
  text "X" at 12246.53,4400.64 h60
  text "ANSI IPC-6012 TYPE 3 CLASS 2" at 12433.48,4400.64 h60
  text "OTHER +/-" at 12433.46,4244.64 h60
  text "BOW & TWIST:" at 11407.23,4087.64 h60
  text "X" at 12246.53,4087.64 h60
  text "ANSI IPC-6012 TYPE 3 CLASS 2" at 12433.48,4087.64 h60
  text "OTHER +/-" at 12433.46,3929.13 h60
  text "DRILLING:" at 11332.46,3790.64 h60
  text "REFERENCE:" at 11407.23,3673.64 h60
  text "X" at 12055.46,3673.64 h60
  text "AS SHOWN" at 12242.46,3673.64 h60
  text "X" at 12956.46,3673.64 h60
  text "NC_DRILL FILES" at 13093.46,3673.64 h60
  text "PTH MIN COPPER THICKNESS:" at 11407.23,3515.64 h60
  text "X" at 12757.46,3515.64 h60
  text "1MIL" at 12894.46,3515.64 h60
  text "OTHER" at 13391.46,3515.64 h60
  text "BOARD FINISH:" at 11332.46,3356.64 h60
  text "SILKSCREEN:" at 11487.68,3238.64 h60
  text "X" at 12436.46,3238.64 h60
  text "TOP" at 12562.46,3238.64 h60
  text "X" at 12946.46,3238.64 h60
  text "BOTTOM" at 13073.46,3238.64 h60
  text "SILKSCREEN COLOR:" at 11487.68,3071.64 h60
  text "X" at 12435.42,3071.64 h60
  text "WHITE" at 12562.46,3071.64 h60
  text "OTHER" at 13073.46,3071.64 h60
  text "SOLDER RESIST COLOR:" at 11487.68,2901.64 h60
  text "GREEN" at 12182.46,2742.44 h60
  text "BLUE" at 12773.46,2742.44 h60
  text "OTHER" at 13311.46,2742.44 h60
  text "X" at 12646,2741 h60
  text "IMMERSION GOLD (ENIG)" at 12393.46,2553.92 h60
  text "ENEPIG" at 13731,2550.64 h60
  text "SURFACE FINISH:" at 11332.46,2549.64 h60
  text "X" at 12206.51,2549.64 h60
  text "IMM. TIN/SILVER OR EQUIV" at 11662,2392.64 h60
  text "OTHER" at 13093.46,2392.64 h60
  text "ARRAY/PANEL:" at 11332.46,2213.64 h60
  text "CUT AND TRIM PER MECH LAYER 1" at 12393.46,2209.35 h60
  text "N.C. ROUTE" at 12393.46,2057.64 h60
  text "X" at 13072.46,2057.64 h60
  text "V. SCORE" at 13259.46,2057.64 h60
  text "CERTIFICATION:" at 11332.46,1920.64 h60
  text "MATERIALS AND WORKMANSHIP FOR ALL PCBS" at 12057.46,1920.64 h60
  text "TO MEET OR EXCEED THE REQUIREMENTS OF:" at 12057.46,1822.64 h60
  text "X" at 11683.96,1686.13 h60
  text "ANSI IPC-A-600F CLASS ->" at 11822.96,1686.13 h60
  text "X" at 13462.02,1686.13 h60
  text "2" at 13580.96,1686.14 h60
  text "1" at 13265.96,1684.64 h60
  text "3" at 13934.96,1684.64 h60
  text "X" at 11686.02,1526.64 h60
  text "UL 94V-0" at 11822.96,1526.64 h60
  text "X" at 12498.02,1526.64 h60
  text "RoHS" at 12634.96,1526.64 h60
  text "OTHER" at 13279.36,1526.64 h60
  text "PER ORDER" at 13676.42,1526.64 h60
  text "ADDITIONAL REQUIREMENTS:" at 11332.46,1385.64 h60
  text "MICROSECTION:" at 11407.23,1270.64 h60
  text "YES" at 12312.96,1270.64 h60
  text "REQUIRED" at 13174.46,1114.49 h60
  text "BARE BOARD ELEC. TEST:" at 11407.23,1111.64 h60
  text "NONE" at 12712.96,1111.64 h60
  text "X" at 13047.46,1111.64 h60
  text "PER ORDER" at 13766.46,1111.64 h60
  text "MANUFACTURER'S UL:" at 11407.23,954.64 h60
  text "RAIL" at 12572.96,950.35 h60
  text "METAL" at 13064.77,950.35 h60
  text "X" at 13440,950 h60
  text "SILK" at 13576.46,950.35 h60
  text ".Layer_Name" at 577,-858.49 h60
M11 Gerber Information:
  lines w10: -292,-930.17 6308,-930.17 ; -292,-726.83 6310,-726.83 ; -292,-523.5 -292,-1133.5 3713,-1133.5 6310,-1133.5 6310,-523.5 -291.5,-523.5 -291.5,-1133.5 1284,-1133.5 ; 2173,-1133.5 2173,-523.5 ; 3440,-726.83 3440,-523.5 ; 4280,-726.83 4280,-523.5 ; 4902,-1140 4902,-937.17
  text "ALL ARTWORK VIEWED FROM TOP SIDE" at -228.5,-655.67 h60
  text "BOARD #:" at 2248,-655.67 h60
  text ".PRJ_Number" at 2793.5,-655.67 h60
  text "REV:" at 3638,-655.67 h60
  text ".PCB_Rev" at 3929.5,-655.67 h60
  text "SVN REV:" at 4476,-655.67 h60
  text ".VersionControl_RevNumber" at 4982,-655.67 h60
  text "LAYER NAME =" at -228.5,-858.49 h60
  text "PLOT NAME =" at -228.5,-1064.34 h60
  text ".plot_File_Name" at 577,-1064.34 h60
  text "GENERATED    :" at 2250,-1064.34 h60
  text ".Print_Date" at 3119.5,-1064.34 h60
  text ".Print_Time" at 3848.5,-1064.34 h60
  text "TEXAS INSTRUMENTS" at 5113,-1064.34 h60
M12 Stackup:
  drawing of 295 lines, arcs and shapes, not listed
  text "Layer" at 8885,7830 h60
  text "Name" at 9294.91,7830 h60
  text "Material" at 11114.37,7830 h60
  text "Thickness" at 11974.14,7830 h60
  text "Constant" at 12623.97,7830 h60
  text "Board Layer Stack" at 13193.83,7830 h60
  text "1" at 8885,7710 h60
  text "Top Overlay" at 9294.91,7710 h60
  text "2" at 8885,7590 h60
  text "Top Solder" at 9294.91,7590 h60
  text "Solder Resist" at 11114.37,7590 h60
  text "0.40mil" at 11974.14,7590 h60
  text "3.5" at 12623.97,7590 h60
  text "3" at 8885,7470 h60
  text "Layer 1 - CIN1 - Top Layer" at 9294.91,7470 h60
  text "Copper" at 11114.37,7470 h60
  text "1.40mil" at 11974.14,7470 h60
  text "4" at 8885,7350 h60
  text "Dielectric1" at 9294.91,7350 h60
  text "370HR" at 11114.37,7350 h60
  text "5.00mil" at 11974.14,7350 h60
  text "4.2" at 12623.97,7350 h60
  text "5" at 8885,7230 h60
  text "Layer 2 - SHLD1 - GND" at 9294.91,7230 h60
  text "Copper" at 11114.37,7230 h60
  text "1.42mil" at 11974.14,7230 h60
  text "6" at 8885,7110 h60
  text "Dielectric 3" at 9294.91,7110 h60
  text "370HR" at 11114.37,7110 h60
  text "45.80mil" at 11974.14,7110 h60
  text "4.2" at 12623.97,7110 h60
  text "7" at 8885,6990 h60
  text "Layer 3 - SHLD2 - PWR" at 9294.91,6990 h60
  text "Copper" at 11114.37,6990 h60
  text "1.42mil" at 11974.14,6990 h60
  text "8" at 8885,6870 h60
  text "Dielectric 2" at 9294.91,6870 h60
  text "370HR" at 11114.37,6870 h60
  text "5.00mil" at 11974.14,6870 h60
  text "4.2" at 12623.97,6870 h60
  text "9" at 8885,6750 h60
  text "Layer 4 - CIN2 - Bottom Layer" at 9294.91,6750 h60
  text "Copper" at 11114.37,6750 h60
  text "1.40mil" at 11974.14,6750 h60
  text "10" at 8885,6630 h60
  text "Bottom Solder" at 9294.91,6630 h60
  text "Solder Resist" at 11114.37,6630 h60
  text "0.40mil" at 11974.14,6630 h60
  text "3.5" at 12623.97,6630 h60
  text "11" at 8885,6510 h60
  text "Bottom Overlay" at 9294.91,6510 h60
  text ".Layer_Name" at 577,-858.49 h60
M13 Component Bodies Top:
  text ".Layer_Name" at 577,-858.49 h60
M14 Component Bodies Bottom:
  text ".Layer_Name" at 577,-858.49 h60
M15 Courtyards Top:
  text ".Layer_Name" at 577,-858.49 h60
M16 Courtyards Bottom:
  text ".Layer_Name" at 577,-858.49 h60
Drill Drawing:
  circle w10: c5758.54,3072.83 r16.54
  circle w10: c5758.54,3072.83 r27.56
  lines w10: 5730.98,2811 5744.76,2811 5744.76,2797.21 5772.32,2797.21 5772.32,2811 5786.1,2811 5786.1,2838.56 5772.32,2838.56 5772.32,2852.34 5744.76,2852.34 5744.76,2838.56 5730.98,2838.56 5730.98,2811 ; 5730.98,2935.02 5744.76,2935.02 5758.54,2921.24 5772.32,2935.02 5786.1,2935.02 5772.32,2948.8 5786.1,2962.58 5772.32,2962.58 5758.54,2976.36 5744.76,2962.58 5730.98,2962.58 5744.76,2948.8 5730.98,2935.02 ; 5730.98,3293.32 5730.98,3307.1 5744.76,3320.88 5730.98,3334.66 5730.98,3348.44 5744.76,3348.44 5758.54,3334.66 5772.32,3348.44 5786.1,3348.44 5786.1,3334.66 5772.32,3320.88 5786.1,3307.1 5786.1,3293.32 5772.32,3293.32 5758.54,3307.1 5744.76,3293.32 5730.98,3293.32 ; 5730.98,3803.21 5744.76,3803.21 5758.54,3789.43 5772.32,3803.21 5786.1,3803.21 5772.32,3816.99 5786.1,3830.77 5772.32,3830.77 5758.54,3844.55 5744.76,3830.77 5730.98,3830.77 5744.76,3816.99 5730.98,3803.21 ; 5742,2816.51 5750.27,2816.51 5750.27,2808.24 5766.81,2808.24 5766.81,2816.51 5775.08,2816.51 5775.08,2833.04 5766.81,2833.04 5766.81,2841.31 5750.27,2841.31 5750.27,2833.04 5742,2833.04 5742,2816.51 ; 5742,2940.53 5750.27,2940.53 5758.54,2932.27 5766.81,2940.53 5775.08,2940.53 5766.81,2948.8 5775.08,2957.07 5766.81,2957.07 5758.54,2965.34 5750.27,2957.07 5742,2957.07 5750.27,2948.8 5742,2940.53 ; 5742,3304.35 5742,3312.61 5750.27,3320.88 5742,3329.15 5742,3337.42 5750.27,3337.42 5758.54,3329.15 5766.81,3337.42 5775.08,3337.42 5775.08,3329.15 5766.81,3320.88 5775.08,3312.61 5775.08,3304.35 5766.81,3304.35 5758.54,3312.61 5750.27,3304.35 5742,3304.35
  lines w12: 5681,2760.01 7656.67,2760.01 ; 5681,3876.25 7656.67,3876.25 ; 6018.36,2635.98 6018.36,4000.27 ; 6350.06,2635.98 6350.06,4000.27 ; 6985.91,2635.98 6985.91,4000.27 ; 7244.71,2635.98 7244.71,4000.27 ; 5681,2635.98 7656.67,2635.98 7656.67,4000.27 5681,4000.27 5681,2635.98
  text "Symbol" at 5755.42,3913.46 h72
  text "Quantity" at 6055.57,3913.46 h72
  text "Finished Hole Size" at 6387.26,3913.46 h72
  text "Plated" at 7023.12,3913.46 h72
  text "Hole Type" at 7281.92,3913.46 h72
  text "4" at 6055.57,3789.43 h60
  text "57.09mil (1.450mm)" at 6387.26,3789.43 h60
  text "NPTH" at 7023.12,3789.43 h60
  text "Round" at 7281.92,3789.43 h60
  text "2" at 6055.57,3665.4 h60
  text "96.00mil (2.438mm)" at 6387.26,3665.4 h60
  text "NPTH" at 7023.12,3665.4 h60
  text "Round" at 7281.92,3665.4 h60
  text "C" at 5730.17,3655.41 h55.12
  text "14" at 6055.57,3541.38 h60
  text "7.87mil (0.200mm)" at 6387.26,3541.38 h60
  text "PTH" at 7023.12,3541.38 h60
  text "Round" at 7281.92,3541.38 h60
  text "E" at 5730.17,3531.38 h55.12
  text "171" at 6055.57,3417.35 h60
  text "10.00mil (0.254mm)" at 6387.26,3417.35 h60
  text "PTH" at 7023.12,3417.35 h60
  text "Round" at 7281.92,3417.35 h60
  text "D" at 5730.17,3407.36 h55.12
  text "26" at 6055.57,3293.32 h60
  text "31.50mil (0.800mm)" at 6387.26,3293.32 h60
  text "PTH" at 7023.12,3293.32 h60
  text "Round" at 7281.92,3293.32 h60
  text "10" at 6055.57,3169.3 h60
  text "40.00mil (1.016mm)" at 6387.26,3169.3 h60
  text "PTH" at 7023.12,3169.3 h60
  text "Round" at 7281.92,3169.3 h60
  text "B" at 5730.17,3159.3 h55.12
  text "4" at 6055.57,3045.27 h60
  text "125.98mil (3.200mm)" at 6387.26,3045.27 h60
  text "PTH" at 7023.12,3045.27 h60
  text "Round" at 7281.92,3045.27 h60
  text "2" at 6055.57,2921.24 h60
  text "19.69mil (0.500mm)" at 6387.26,2921.24 h60
  text "PTH" at 7023.12,2921.24 h60
  text "Slot" at 7281.92,2921.24 h60
  text "1" at 6055.57,2797.21 h60
  text "19.69mil (0.500mm)" at 6387.26,2797.21 h60
  text "PTH" at 7023.12,2797.21 h60
  text "Slot" at 7281.92,2797.21 h60
  text "234 Total" at 6055.57,2673.19 h60
  text "Slot definitions :" at 5755.42,2586.37 h60
  text "Routed Path Length" at 6204.86,2586.37 h60
  text "= Calculated from tool start centre position to tool end centre position." at 6743.21,2586.37 h60
  text "Hole Length" at 6204.86,2536.76 h60
  text "= Routed Path Length + Tool Size = Slot length as defined in the PCB layout" at 6543.91,2536.76 h60
  text ".Layer_Name" at 577,-858.49 h60

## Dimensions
0,-400 to 1000,-400 on M2 Board Dimensions
0,0 to 0,4000 on M2 Board Dimensions
0,0 to 5000,0 on M2 Board Dimensions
